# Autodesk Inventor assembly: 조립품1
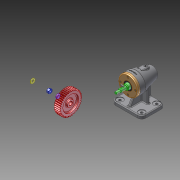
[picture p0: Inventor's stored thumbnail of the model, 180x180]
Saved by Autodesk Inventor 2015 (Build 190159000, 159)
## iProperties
Created: 2024-12
Part Number: 조립품1
Document SubType Name: Assembly
Designer: 102566
Author: 102566
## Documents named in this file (13)
- C:\Users\102566\Desktop\741204V1008\조립품1.iam
- C:\Users\102566\Desktop\741204V1008\본체.ipt
- C:\Users\102566\Desktop\741204V1008\앵귤러 볼 베어링 7003A.ipt
- C:\Users\102566\Desktop\741204V1008\앵귤러 볼 제어링 7204A.ipt
- C:\Users\102566\Desktop\741204V1008\오일 실 20 32 8.ipt
- C:\Users\102566\Desktop\741204V1008\축.ipt
- C:\Users\102566\Desktop\741204V1008\커버.ipt
- C:\Users\102566\Desktop\741204V1008\육각 소켓 머리 볼트 M4x10.ipt
- C:\Users\102566\Desktop\741204V1008\스퍼기어.ipt
- C:\Users\102566\Desktop\741204V1008\스프링 와셔 M8.ipt
- C:\Users\102566\Desktop\741204V1008\육각 너트 M8.ipt
- C:\Users\102566\Desktop\741204V1008\평와셔 M8.ipt
- C:\Users\102566\Desktop\741204V1008\평행 키 4x4x14.ipt
